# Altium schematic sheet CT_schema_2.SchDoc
size 313 x 185 mm
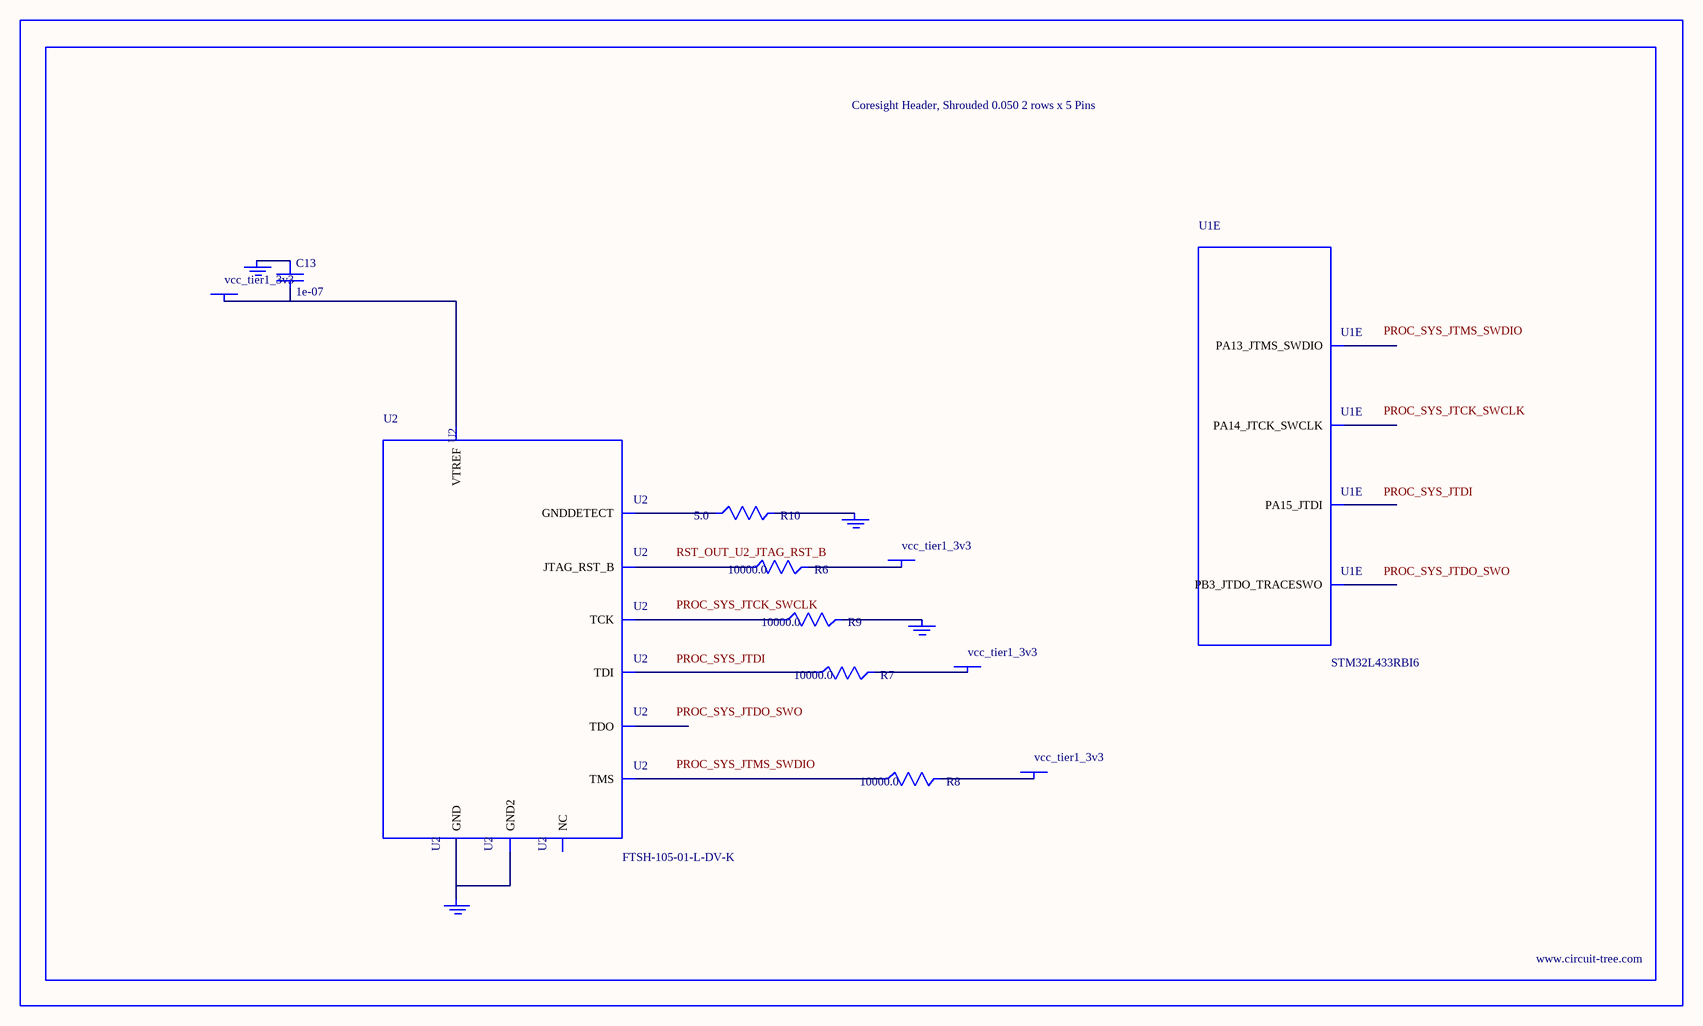
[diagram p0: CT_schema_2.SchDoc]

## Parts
BORDER1  (no value)
C13  1e-07  [C0402]
GND_INSTANCE_1_0  (no value)
GND_INSTANCE_1_1  (no value)
GND_INSTANCE_1_2  (no value)
GND_INSTANCE_1_3  (no value)
POWER_INSTANCE_1_0  vcc_tier1_3v3
POWER_INSTANCE_1_1  vcc_tier1_3v3
POWER_INSTANCE_1_2  vcc_tier1_3v3
POWER_INSTANCE_1_3  vcc_tier1_3v3
R6  10000.0  [R0603]
R7  10000.0  [R0603]
R8  10000.0  [R0603]
R9  10000.0  [R0603]
R10  5.0  [R0603]
U1  STM32L433RBI6  [UFBGA64]  (part E of 7)
U2  FTSH-105-01-L-DV-K  [SAMTEC_FTSH-105-01-L-DV-K]

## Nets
NetC13_1: C13.1 GND_INSTANCE_1_0.0(GND)
NetC13_2: C13.2 POWER_INSTANCE_1_0.0(PWR) U2.1(VTREF)
NetGND_INSTANCE_1_1_0: GND_INSTANCE_1_1.0(GND) R9.2
NetGND_INSTANCE_1_2_0: GND_INSTANCE_1_2.0(GND) R10.2
NetGND_INSTANCE_1_3_0: GND_INSTANCE_1_3.0(GND) U2.3(GND) U2.5(GND2)
NetPOWER_INSTANCE_1_1_0: POWER_INSTANCE_1_1.0(PWR) R8.2
NetPOWER_INSTANCE_1_2_0: POWER_INSTANCE_1_2.0(PWR) R7.2
NetPOWER_INSTANCE_1_3_0: POWER_INSTANCE_1_3.0(PWR) R6.2
NetR6_1: R6.1 U2.10(JTAG_RST_B)
NetR7_1: R7.1 U2.8(TDI)
NetR8_1: R8.1 U2.2(TMS)
NetR9_1: R9.1 U2.4(TCK)
NetR10_1: R10.1 U2.9(GNDDETECT)

Not connected (* = marked no-connect by the designer): U1 A5(PB3_JTDO_TRACESWO) A6(PA15_JTDI) A7(PA14_JTCK_SWCLK) A8(PA13_JTMS_SWDIO); U2 6(TDO) 7(NC)

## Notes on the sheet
- Labels drawn without touching a wire or pin: PROC_SYS_JTCK_SWCLK, PROC_SYS_JTDI, PROC_SYS_JTDO_SWO, PROC_SYS_JTMS_SWDIO, RST_OUT_U2_JTAG_RST_B

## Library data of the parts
BORDER1 = BORDER_PAGE1
C13 = C0402C104K3RACTU
GND_INSTANCE_1_0-GND_INSTANCE_1_3 = GND
POWER_INSTANCE_1_0-POWER_INSTANCE_1_3 = PWR
R6-R9 = RC0603JR-0710KL
R10 = ERJ-3GEYJ5R1V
